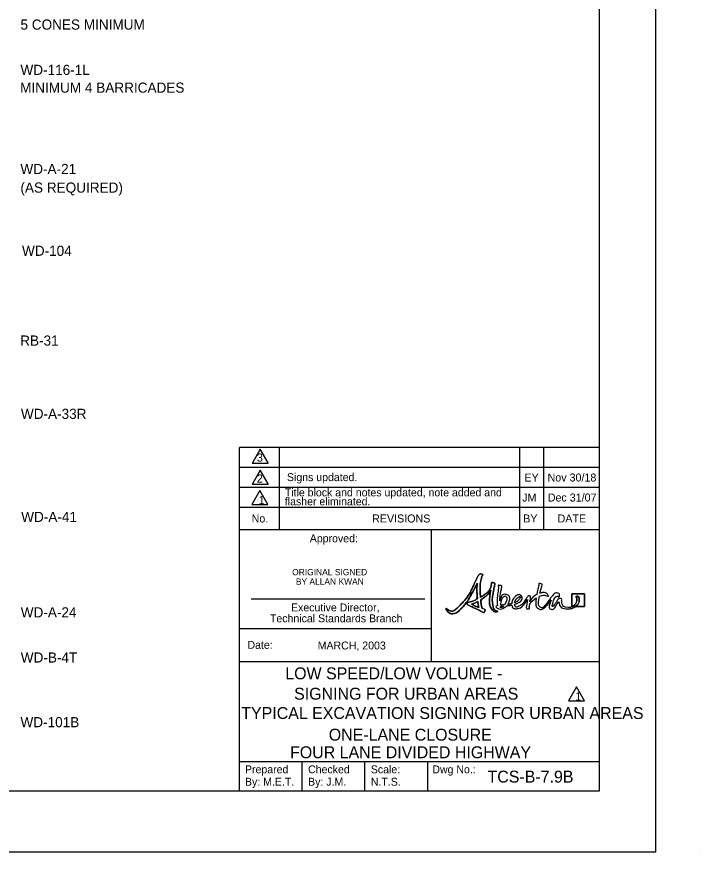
# Model space of a CAD drawing. Extents: x 1056 to 1280, y 240 to 519.
# Drawn here: x 1158.2 to 1279.5, y 239.8 to 388 of the extents above; entities that cross this region are included whole.
import ezdxf

# ---------------------------------------------------------------- set-up
doc = ezdxf.new("R2010")
doc.units = 0
for name, color, linetype in [('Level 10', 7, 'Continuous'), ('Level 11', 7, 'Continuous'), ('Level 17', 7, 'Continuous'), ('Level 2', 7, 'Continuous'), ('Level 29', 7, 'Continuous'), ('Level 53', 7, 'Continuous'), ('Level 60', 7, 'Continuous'), ('Level 9', 7, 'Continuous')]:
    doc.layers.add(name, color=color, linetype=linetype)

msp = doc.modelspace()

# ---------------------------------------------------------------- linework, layer by layer
at = {"layer": 'Level 10'}
for p, q in [((1261.59, 311.64), (1197.71, 311.64)), ((1261.59, 308.09), (1197.71, 308.09)), ((1261.59, 304.54), (1197.71, 304.54)), ((1261.59, 300.99), (1197.71, 300.99)), ((1197.72, 297.09), (1261.59, 297.09)), ((1261.56, 250.63), (1261.56, 250.63)), ((1279.51, 239.82), (1279.51, 239.82))]:
    msp.add_line(p, q, dxfattribs=at)
for points in [[(1055.56, 518.82), (1271.56, 518.82), (1271.56, 239.82), (1055.56, 239.82)], [(1074.69, 508.01), (1261.56, 508.01), (1261.56, 250.63), (1074.69, 250.63)], [(1201.34, 303.98), (1199.92, 301.5), (1202.76, 301.5)]]:
    msp.add_lwpolyline(points, close=True, dxfattribs=at)
at = {"layer": 'Level 11'}
msp.add_line((1231.79, 297.09), (1231.79, 297.09), dxfattribs=at)
at = {"layer": 'Level 29'}
for p, q in [((1197.72, 305.17), (1197.72, 311.64)), ((1204.81, 305.17), (1204.81, 311.64)), ((1247.4, 311.64), (1247.4, 297.09)), ((1251.71, 311.64), (1251.71, 297.09)), ((1197.72, 297.09), (1197.72, 305.17)), ((1204.81, 297.09), (1204.81, 305.17))]:
    msp.add_line(p, q, dxfattribs=at)
for points in [[(1201.42, 311.31), (1200.03, 308.88)], [(1202.81, 308.88), (1201.42, 311.31)], [(1200.03, 308.88), (1200, 308.84), (1202.84, 308.84), (1202.81, 308.88)], [(1201.42, 307.59), (1200.03, 305.17)], [(1202.81, 305.17), (1201.42, 307.59)], [(1200.03, 305.17), (1200, 305.12), (1202.84, 305.12), (1202.81, 305.17)]]:
    msp.add_lwpolyline(points, dxfattribs=at)
at = {"layer": 'Level 53'}
msp.add_line((1257.36, 283.41), (1256.8, 283.41), dxfattribs=at)
msp.add_lwpolyline([(1257.36, 283.41), (1258.97, 283.41), (1258.97, 285.65), (1256.74, 285.65), (1256.74, 283.41), (1256.8, 283.41)], dxfattribs=at)
for points, degree in [([(1243.37, 282.61), (1243.13, 282.64), (1242.82, 282.97), (1242.72, 283.5), (1242.55, 284.47), (1242.65, 285.42), (1242.93, 286.85), (1242.99, 287.11), (1243.17, 287.58), (1242.59, 287.67), (1242.4, 287.7), (1242.5, 287.61), (1242.45, 287.36), (1242.22, 286.3), (1241.36, 285.54), (1240.49, 285.03), (1240.4, 286.24), (1240.43, 287.59), (1240.66, 288.41), (1240.86, 289.11), (1241.08, 288.98), (1240.8, 289.13), (1240.5, 289.28), (1240.18, 289.08), (1239.92, 288.56), (1239.66, 288.04), (1238.46, 285.22), (1236.55, 283.32), (1235.57, 282.35), (1234.69, 282.85), (1234.51, 283), (1234.37, 283.12), (1234.32, 282.93), (1234.49, 282.74), (1235.29, 281.89), (1236.44, 282.38), (1236.86, 282.8), (1238.02, 283.96), (1239.38, 286.46), (1239.92, 287.53), (1239.87, 286.93), (1239.86, 285.93), (1239.97, 284.75), (1239.38, 284.46), (1238.84, 284.29), (1238.59, 284.23), (1238.32, 284.16), (1238.16, 284.05), (1238.15, 283.92), (1238.15, 283.78), (1238.33, 283.67), (1238.59, 283.54), (1239.06, 283.32), (1240.43, 282.67), (1240.77, 282.47), (1241.06, 282.31), (1241.2, 282.44), (1241.29, 282.62), (1241.4, 282.85), (1241.09, 282.99), (1240.79, 283.08), (1240.68, 283.48), (1240.59, 284.01), (1240.53, 284.6), (1241.22, 285.03), (1241.91, 285.6), (1242.31, 286.32), (1242.21, 285.72), (1241.95, 283.69), (1242.59, 282.83), (1242.73, 282.64), (1243.04, 282.44), (1243.35, 282.47), (1243.49, 282.48), (1243.56, 282.58), (1243.55, 282.61), (1243.54, 282.63), (1243.45, 282.59), (1243.37, 282.61)], 3), ([(1240.49, 285.03), (1240.4, 286.24), (1240.43, 287.59), (1240.66, 288.41), (1240.86, 289.11), (1241.08, 288.98), (1240.8, 289.13), (1240.5, 289.28), (1240.18, 289.08), (1239.92, 288.56), (1239.66, 288.04), (1238.46, 285.22), (1236.55, 283.32), (1235.57, 282.35), (1234.69, 282.85), (1234.51, 283), (1234.37, 283.12), (1234.32, 282.93), (1234.49, 282.74), (1235.29, 281.89), (1236.44, 282.38), (1236.86, 282.8), (1238.02, 283.96), (1239.38, 286.46), (1239.92, 287.53)], 3), ([(1243.37, 282.61), (1243.13, 282.64), (1242.82, 282.97), (1242.72, 283.5), (1242.55, 284.47), (1242.65, 285.42), (1242.93, 286.85), (1242.99, 287.11), (1243.17, 287.58), (1242.59, 287.67), (1242.4, 287.7), (1242.5, 287.61), (1242.45, 287.36), (1242.22, 286.3), (1241.36, 285.54), (1240.49, 285.03)], 3), ([(1239.92, 287.53), (1239.87, 286.93), (1239.86, 285.93), (1239.97, 284.75)], 2), ([(1240.53, 284.6), (1241.22, 285.03), (1241.91, 285.6), (1242.31, 286.32)], 2), ([(1242.31, 286.32), (1242.21, 285.72), (1241.95, 283.69), (1242.59, 282.83), (1242.73, 282.64), (1243.04, 282.44), (1243.35, 282.47), (1243.49, 282.48), (1243.56, 282.58), (1243.55, 282.61), (1243.54, 282.63), (1243.45, 282.59), (1243.37, 282.61)], 3), ([(1243.91, 284.45), (1243.95, 285.02), (1244.04, 285.71), (1244.17, 286.35), (1244.23, 286.62), (1244.41, 287.09), (1243.83, 287.18), (1243.64, 287.2), (1243.67, 287.12), (1243.68, 286.87), (1243.71, 286.53), (1243.33, 284.49), (1243.53, 283.59)], 3), ([(1251.06, 285.79), (1251.13, 286.09), (1251.2, 286.39), (1251.28, 286.68), (1251.36, 286.95), (1251.58, 287.42), (1251, 287.51), (1250.82, 287.53), (1250.9, 287.45), (1250.84, 287.2), (1250.73, 286.74), (1250.58, 286.15), (1250.48, 285.55)], 3), ([(1239.97, 284.75), (1239.38, 284.46), (1238.84, 284.29), (1238.59, 284.23), (1238.32, 284.16), (1238.16, 284.05), (1238.15, 283.92), (1238.15, 283.78), (1238.33, 283.67), (1238.59, 283.54), (1239.06, 283.32), (1240.43, 282.67), (1240.77, 282.47), (1241.06, 282.31), (1241.2, 282.44), (1241.29, 282.62), (1241.4, 282.85), (1241.09, 282.99), (1240.79, 283.08)], 3), ([(1240.79, 283.08), (1240.68, 283.48), (1240.59, 284.01), (1240.53, 284.6)], 2), ([(1245.34, 283.79), (1245.76, 284.46), (1245.72, 285.37), (1245.12, 285.52), (1244.41, 285.7), (1244.06, 285.02), (1243.91, 284.45)], 3), ([(1244.06, 283.66), (1244.15, 284.37), (1244.52, 285.37), (1244.99, 285.21), (1245.26, 285.12), (1245.11, 284.28), (1244.77, 283.72)], 3), ([(1246.57, 283.81), (1246.67, 283.84), (1246.75, 283.87), (1246.83, 283.9), (1247.71, 284.29), (1248.01, 284.88), (1247.79, 285.24), (1247.57, 285.58), (1246.97, 285.48), (1246.48, 284.97), (1246.25, 284.72), (1246.07, 284.29), (1246.04, 283.9)], 3), ([(1246.05, 283.68), (1246.1, 283.29), (1246.36, 282.99), (1246.95, 283.04), (1247.8, 283.12), (1248.55, 284.16), (1248.83, 284.66)], 3), ([(1249.25, 284.22), (1249.3, 284.5), (1249.39, 284.81), (1249.39, 285.01), (1249.4, 285.23), (1249.25, 285.28), (1249.19, 285.29), (1249.07, 285.33), (1248.91, 285.27), (1248.76, 285.05), (1248.41, 284.56), (1247.96, 283.77), (1247.28, 283.44), (1246.8, 283.2), (1246.58, 283.44), (1246.57, 283.81)], 3), ([(1247.04, 284.93), (1247.34, 285.2), (1247.49, 285.18), (1247.52, 285.11), (1247.61, 284.95), (1247.26, 284.39), (1246.59, 284.08)], 3), ([(1246.59, 284.08), (1246.65, 284.38), (1246.81, 284.71), (1247.04, 284.93)], 2), ([(1248.83, 284.66), (1248.78, 284.13), (1248.43, 282.95), (1249.03, 283.01), (1249.26, 283.04), (1249.16, 283.08), (1249.17, 283.28), (1249.23, 283.98), (1249.81, 284.58), (1250.4, 284.95)], 3), ([(1250.48, 285.55), (1250.01, 285.28), (1249.57, 284.82), (1249.25, 284.22)], 2), ([(1250.4, 284.95), (1250.29, 284.08), (1250.33, 283.31), (1250.72, 283.07), (1251.44, 282.62), (1252.47, 283.8), (1253.03, 284.53)], 3), ([(1256.12, 283.22), (1255.2, 283.22), (1254.96, 283.93), (1254.92, 284.28), (1254.89, 284.51), (1254.94, 284.85), (1254.54, 284.81), (1254.25, 284.78), (1254, 284.23), (1253.64, 283.76), (1253.33, 283.36), (1253.19, 283.4), (1253.26, 283.74), (1253.35, 284.17), (1253.71, 285.18), (1254.12, 285.25), (1254.31, 285.28), (1254.38, 284.95), (1254.46, 285.16), (1254.55, 285.37), (1254.47, 285.82), (1254.05, 285.82), (1253.75, 285.82), (1253.4, 285.5), (1253.1, 285.15), (1252.85, 284.83), (1251.56, 282.94), (1251.03, 283.35), (1250.77, 283.54), (1250.79, 284.32), (1250.95, 285.23)], 3), ([(1250.95, 285.23), (1251.59, 285.48), (1252.12, 285.4), (1252.42, 285.26), (1252.57, 285.18), (1252.59, 285.2), (1252.53, 285.36), (1252.44, 285.6), (1251.92, 285.97), (1251.12, 285.8), (1251.1, 285.8), (1251.08, 285.79), (1251.06, 285.79)], 3), ([(1256.74, 285.65), (1256.74, 285.65), (1256.74, 283.41), (1256.74, 283.41), (1256.74, 283.41), (1256.8, 283.41), (1256.8, 283.41), (1257.29, 283.7), (1257.61, 284.26), (1257.61, 284.72), (1257.61, 285.11), (1257.4, 285.09), (1257.43, 285.14), (1257.5, 285.3), (1257.99, 285.21), (1258.02, 284.66), (1258.04, 284.18), (1257.8, 283.73), (1257.36, 283.41), (1257.36, 283.41), (1258.97, 283.41), (1258.97, 283.41), (1258.97, 283.41), (1258.97, 285.65), (1258.97, 285.65), (1258.97, 285.65), (1256.74, 285.65), (1256.74, 285.65)], 3), ([(1256.8, 283.41), (1257.29, 283.7), (1257.61, 284.26), (1257.61, 284.72), (1257.61, 285.11), (1257.4, 285.09), (1257.43, 285.14), (1257.5, 285.3), (1257.99, 285.21), (1258.02, 284.66), (1258.04, 284.18), (1257.8, 283.73), (1257.36, 283.41)], 3), ([(1238.9, 283.82), (1239.21, 283.93), (1239.6, 284.1), (1240.01, 284.31)], 2), ([(1238.9, 283.82), (1239.21, 283.93), (1239.6, 284.1), (1240.01, 284.31), (1240.07, 283.84), (1240.13, 283.5), (1240.2, 283.24), (1239.89, 283.35), (1239.46, 283.53), (1238.9, 283.82)], 3), ([(1240.2, 283.24), (1239.89, 283.35), (1239.46, 283.53), (1238.9, 283.82)], 2), ([(1240.01, 284.31), (1240.07, 283.84), (1240.13, 283.5), (1240.2, 283.24)], 2), ([(1243.53, 283.59), (1243.28, 283.51), (1243.17, 283.32), (1243.5, 283.13), (1243.72, 282.99), (1244.21, 282.94), (1244.7, 283.19), (1244.88, 283.27), (1245.04, 283.4), (1245.16, 283.54)], 3), ([(1243.98, 283.22), (1244.01, 283.25), (1244.03, 283.29), (1244.03, 283.34), (1244.03, 283.37), (1244.03, 283.4), (1244.04, 283.44)], 3), ([(1244.18, 283.23), (1244.1, 283.21), (1244.03, 283.21), (1243.98, 283.22)], 2), ([(1244.04, 283.44), (1244.16, 283.44), (1244.36, 283.46), (1244.59, 283.48)], 2), ([(1244.77, 283.72), (1244.55, 283.7), (1244.31, 283.68), (1244.06, 283.66)], 2), ([(1244.59, 283.48), (1244.47, 283.34), (1244.33, 283.25), (1244.18, 283.23)], 2), ([(1245.16, 283.54), (1245.46, 283.58), (1245.77, 283.63), (1246.05, 283.68)], 2), ([(1246.04, 283.9), (1245.84, 283.86), (1245.61, 283.82), (1245.34, 283.79)], 2), ([(1253.03, 284.53), (1252.74, 283.89), (1252.58, 283.06), (1253.01, 282.93), (1253.52, 282.78), (1253.91, 283.62), (1254.38, 284.26)], 3), ([(1254.38, 284.26), (1254.43, 283.8), (1254.74, 283.01), (1255.98, 283.01), (1256.53, 283.01), (1257.01, 283.17), (1257.36, 283.41)], 3), ([(1256.8, 283.41), (1256.6, 283.29), (1256.37, 283.22), (1256.12, 283.22)], 2)]:
    msp.add_open_spline(points, degree=degree, dxfattribs=at)
at = {"layer": 'Level 60'}
for p, q in [((1197.72, 250.63), (1197.72, 297.09)), ((1231.77, 297.09), (1231.77, 273.68)), ((1199.83, 284.78), (1230.63, 284.78)), ((1197.72, 279.53), (1231.77, 279.53)), ((1197.72, 273.68), (1261.56, 273.68)), ((1197.72, 255.95), (1261.56, 255.95)), ((1208.85, 250.63), (1208.85, 255.95)), ((1219.98, 250.63), (1219.98, 255.95)), ((1231.11, 255.95), (1231.11, 250.63)), ((1213.18, 250.63), (1213.18, 250.63))]:
    msp.add_line(p, q, dxfattribs=at)
msp.add_lwpolyline([(1257.53, 269.16), (1256.11, 266.69), (1258.95, 266.69)], close=True, dxfattribs=at)

# ---------------------------------------------------------------- texts
at = {"layer": 'Level 10'}
for s, p in [('5 CONES MINIMUM', (1158.87, 385.75)), ('WD-116-1L', (1158.87, 377.71)), ('MINIMUM 4 BARRICADES', (1158.81, 374.56)), ('WD-A-21', (1158.86, 360.13)), ('(AS REQUIRED)', (1158.86, 356.83)), ('WD-104', (1159.14, 345.62)), ('RB-31', (1158.82, 329.69)), ('WD-A-33R', (1158.95, 316.69)), ('WD-A-41', (1159, 298.41)), ('WD-A-24', (1158.92, 281.48)), ('WD-B-4T', (1158.92, 273.47)), ('WD-101B', (1158.87, 262))]:
    msp.add_text(s, height=1.8, dxfattribs=at).set_placement(p)
for s, height, p in [('3', 1.45, (1200.81, 309.11)), ('2', 1.45, (1200.79, 305.39)), ('1', 1.45, (1201.11, 301.56)), ('JM', 1.419, (1247.9, 302.04)), ('Dec 31/07', 1.419, (1252.44, 302.04)), ('No.', 1.419, (1199.89, 298.32)), ('REVISIONS', 1.419, (1221.27, 298.32)), ('BY', 1.419, (1248.08, 298.32)), ('DATE', 1.419, (1254.18, 298.32))]:
    msp.add_text(s, height=height, rotation=360, dxfattribs=at).set_placement(p)
at = {"layer": 'Level 17'}
for s, p in [('EY', (1248.3, 305.59)), ('Nov 30/18', (1252.41, 305.59))]:
    msp.add_text(s, height=1.419, rotation=360, dxfattribs=at).set_placement(p)
for s, p in [('ORIGINAL SIGNED', (1207.08, 288.96)), ('BY ALLAN KWAN', (1207.73, 287.28))]:
    msp.add_text(s, height=1.12, dxfattribs=at).set_placement(p)
at = {"layer": 'Level 2'}
for s, p in [('LOW SPEED/LOW VOLUME -', (1205.86, 270.5)), ('SIGNING FOR URBAN AREAS', (1207.43, 266.89))]:
    msp.add_text(s, height=2.116, rotation=360, dxfattribs=at).set_placement(p)
at = {"layer": 'Level 60'}
for s, height, p in [('Approved:', 1.4, (1210.21, 294.81)), ('Executive Director,', 1.4, (1206.88, 282.55)), ('Technical Standards Branch', 1.4, (1203.14, 280.62)), ('MARCH, 2003', 1.4, (1211.62, 275.8)), ('TYPICAL EXCAVATION SIGNING FOR URBAN AREAS', 2.116, (1198.05, 263.46)), ('TCS-B-7.9B', 2.116, (1241.75, 252.18))]:
    msp.add_text(s, height=height, dxfattribs=at).set_placement(p)
for s, height, p in [('Date:', 1.4, (1199.15, 275.91)), ('1', 1.45, (1257.31, 266.75)), ('ONE-LANE CLOSURE', 2.116, (1213.58, 259.62)), ('FOUR LANE DIVIDED HIGHWAY', 2.116, (1206.71, 256.5)), ('Prepared', 1.4, (1198.71, 253.83)), ('Checked', 1.4, (1209.91, 253.83)), ('Scale:', 1.4, (1221.04, 253.83)), ('Dwg No.:', 1.4, (1231.96, 253.83)), ('By: M.E.T.', 1.4, (1198.71, 251.63)), ('By: J.M.', 1.4, (1209.91, 251.63)), ('N.T.S.', 1.4, (1221.04, 251.63))]:
    msp.add_text(s, height=height, rotation=360, dxfattribs=at).set_placement(p)
at = {"layer": 'Level 9'}
for s, p in [('Signs updated.', (1206.16, 305.66)), ('Title block and notes updated, note added and ', (1205.78, 302.95)), ('flasher eliminated.', (1205.78, 301.36))]:
    msp.add_text(s, height=1.4, dxfattribs=at).set_placement(p)

doc.saveas('drawing.dxf')
